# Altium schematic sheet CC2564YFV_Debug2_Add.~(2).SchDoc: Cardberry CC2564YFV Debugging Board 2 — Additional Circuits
size A4; DrawnBy: Pavel Ivshin; Engineer: Pavel Ivshin; Organization: Cardberry; Revision: 0; SheetNumber: 2; SheetTotal: 2
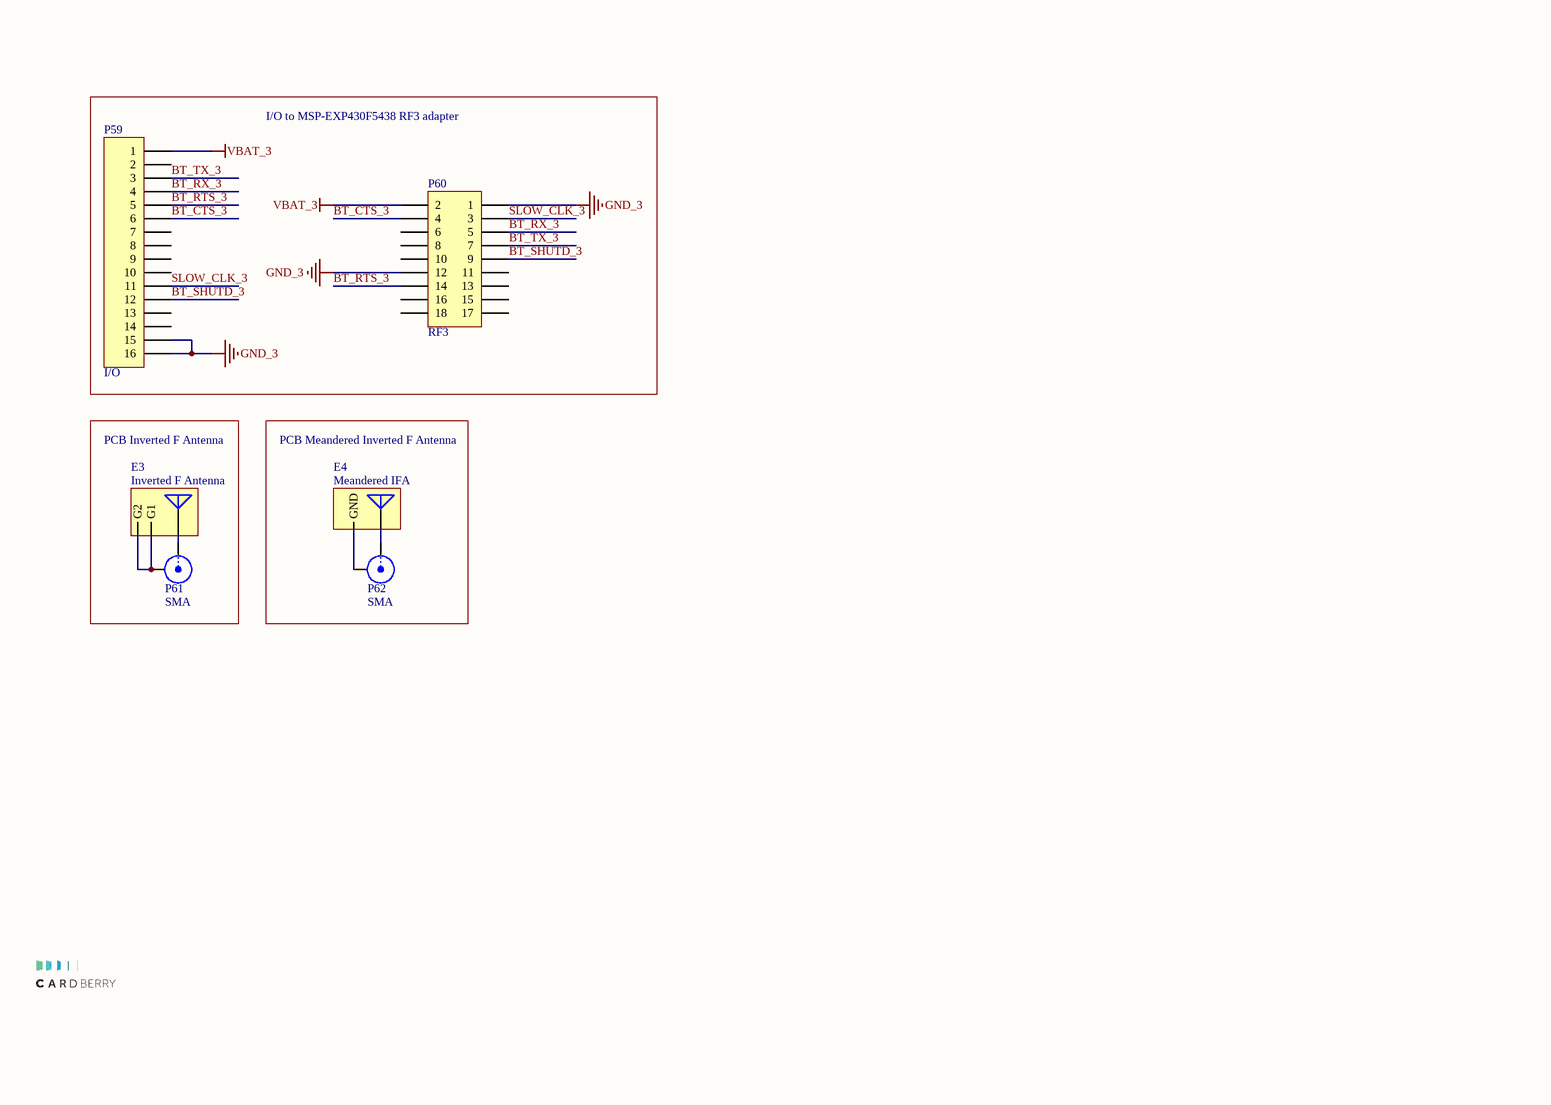
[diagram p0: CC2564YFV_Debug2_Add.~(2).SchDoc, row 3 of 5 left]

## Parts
E3  Inverted F Antenna  [Inverted_F_Antenna]
E4  Meandered IFA  [Meandered_IFA]  (no BOM)
P59  I/O  [HDR1X16]
P60  RF3  [HDR2X9]
P61  SMA  [SMA]
P62  SMA  [SMA]

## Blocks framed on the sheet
I/O to MSP-EXP430F5438 RF3 adapter: P59 P60
PCB Inverted F Antenna: E3 P61
PCB Meandered Inverted F Antenna: E4 P62

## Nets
GND_3: P59.15 P59.16 P60.1 P60.12
VBAT_3: P59.1 P60.2
BT_CTS_3: P59.6 P60.4
BT_RTS_3: P59.5 P60.14
BT_RX_3: P59.4 P60.5
BT_SHUTD_3: P59.12 P60.9
BT_TX_3: P59.3 P60.7
SLOW_CLK_3: P59.11 P60.3
NetE3_1: E3.1(FEED) P61.1(X)
NetE3_2: E3.2(G1) E3.3(G2) P61.2(Y)
NetE4_1: E4.1(FEED) P62.1(X)
NetE4_2: E4.2(GND) P62.2(Y)

Not connected (* = marked no-connect by the designer): P59 2 7 8 9 10 13 14; P60 6 8 10 11 13 15 16 17 18

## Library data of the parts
E3 = Inverted F Antenna: Inverted F Antenna (Design Note DN0007; SWRU120B)
E4 = Meandered IFA: Meandered Inverted F Antenna (Application Note AN043; SWRA117D)
P59 = Header 16: Header, 16-Pin
P60 = Header 9X2: Header, 9-Pin, Dual row
P61 P62 = SMA: SMA Generic Connector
